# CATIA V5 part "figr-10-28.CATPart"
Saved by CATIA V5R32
Part number: Part1
Bounding box of the stored display mesh (mm): x -60 to 70, y 0 to 100.393, z 0 to 0
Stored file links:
  D:\PROJECTS\Project 2022\CATIA V5 6R 2022\Resources\Part Files\c10_catia_v5_6r2022_prt\c10_catia_v5_6r2022_prt\figr-10-28.CATPart
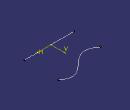
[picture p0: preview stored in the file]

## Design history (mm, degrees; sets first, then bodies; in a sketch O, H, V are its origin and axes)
Body1 (main body)
  Sketch1 on xy-plane, origin (0, 0, 0), H (1, 0, 0), V (0, 1, 0)
    line L1 (-60, 0) -> (70, 0)
    point P1 (-60, 0)
    coincidence: P1 H
    horizontal: L1 H
  Sketch2 on xy-plane, origin (0, 0, 0), H (1, 0, 0), V (0, 1, 0)
    spline S1 through (-60, 70) (-20, 60) (40, 100) (70, 90)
